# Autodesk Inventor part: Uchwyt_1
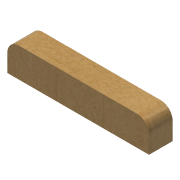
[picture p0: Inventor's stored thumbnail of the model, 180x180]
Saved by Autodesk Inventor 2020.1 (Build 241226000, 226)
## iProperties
Created: 2005-09
Part Number: Uchwyt_1
Document SubType Name: Modeling
Designer: F.Stasiak
Density: 1 g/cm^3
Material: Ogólny
Appearance: Sosna żółta — pełna — barwiona na jasno — niski połysk
Manager: www.cadconsulting.pl
Company: Fabian Stasiak CAD Consulting
Author: F.Stasiak
Subject: Zbiór ćwiczeń. Autodesk Inventor 2020. Kurs podstawowy
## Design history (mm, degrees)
sketch "Szkic1"
  geometry: L1 (-60, 25)-(60, 25); L2 (60, 25)-(60, 0); L3 (60, 0)-(-60, 0); L4 (-60, 0)-(-60, 25); 2 further points
  constraints: 8 end point, 2 parallel, 1 coincident, 1 horizontal, 1 midpoint, 1 perpendicular
  dimensions: "d0" = 25 distance of L1.end L2.end; "d1" = 120 distance between parallel lines of L2 L4
extrude "Wyciągnięcie proste1" new body sketch "Szkic1" distance "d2" = 20; taper "d3" = 0 deg
fillet "Zaokrąglenie1" dims "d4" = 10
node "Bryła1"
node "Korpusy bryłowe"
node "Korpusy powierzchniowe"
